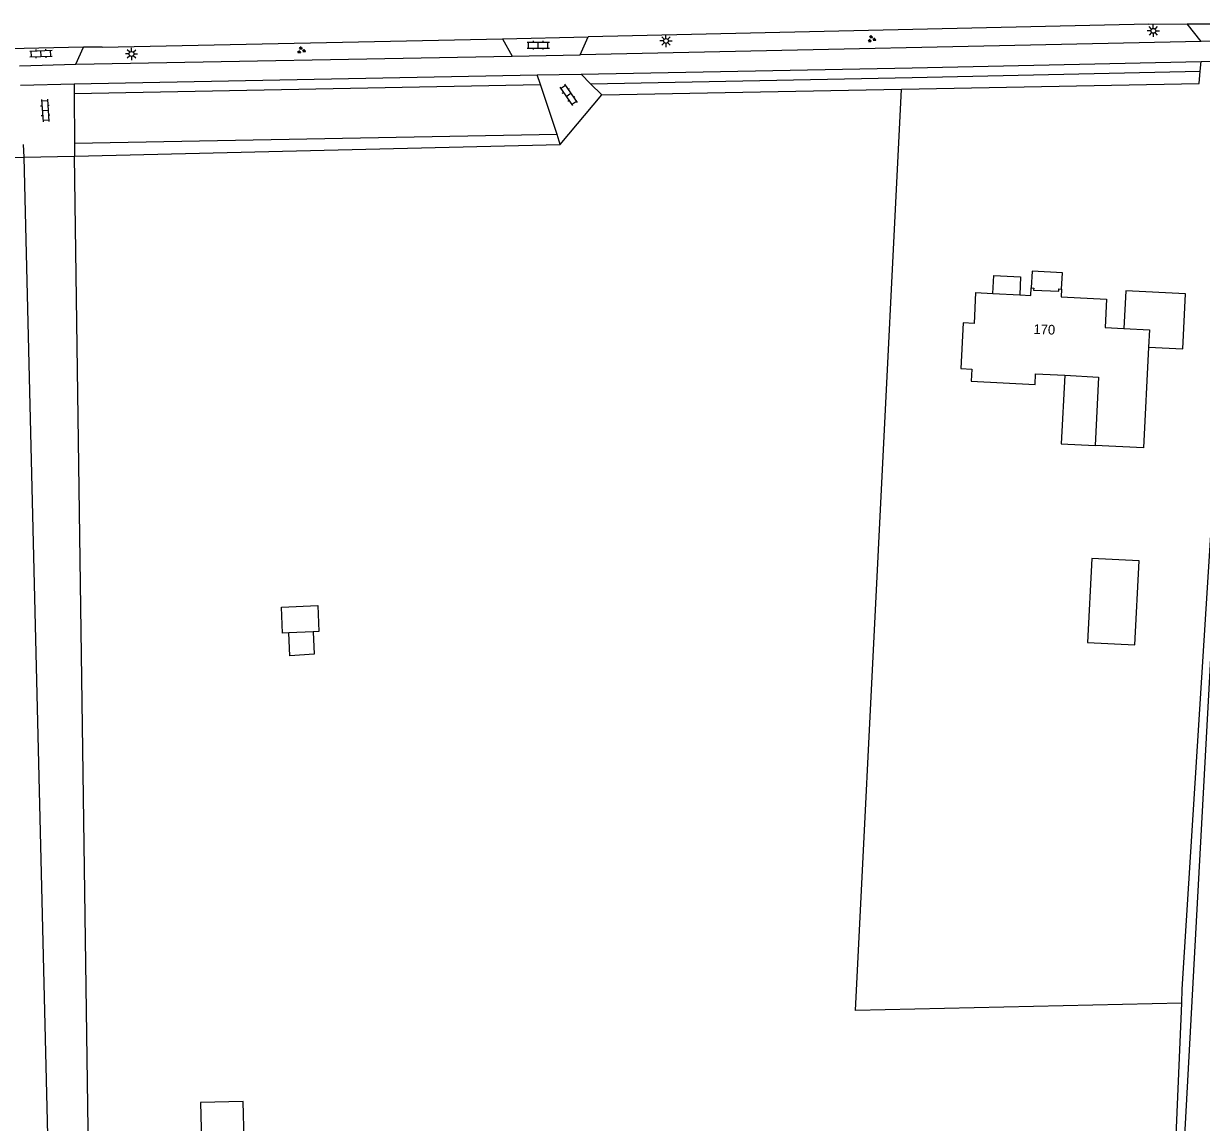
# Model space of a CAD drawing. Extents: x 128999 to 131010, y 395498 to 399007.
# Drawn here: x 130782.7 to 130904.2, y 396021.5 to 396134.9 of the extents above; entities that cross this region are included whole.
import ezdxf

# ---------------------------------------------------------------- set-up
doc = ezdxf.new("R2010")
doc.units = 0
for name, color, linetype in [('gg-afsc-erfafscheiding', 7, 'Continuous'), ('gg-anno-huisnummerreeks BGT', 7, 'Continuous'), ('gg-bbg-bijgebouw', 7, 'Continuous'), ('gg-bbg-gedigitaliseerde bebouwing', 7, 'Continuous'), ('gg-bbg-gedigitaliseerde bijgebouw', 7, 'Continuous'), ('gg-bbg-hoofdgebouw', 7, 'Continuous'), ('gg-bbg-luifel en loopbrug', 7, 'Continuous'), ('gg-knt-onverhard', 7, 'Continuous'), ('gg-knt-verharding', 7, 'Continuous'), ('gt-grn-groengrens', 7, 'Continuous'), ('gt-grn-groengrens NZ', 7, 'Continuous'), ('gt-symb-groenvak', 7, 'Continuous'), ('gt-symb-klinker verharding', 7, 'Continuous'), ('gt-symb-lichtmast', 7, 'Continuous')]:
    doc.layers.add(name, color=color, linetype=linetype)

# ---------------------------------------------------------------- blocks, each defined once
blk = doc.blocks.new('gt0-LMAST')
at = {"layer": 'gt-symb-lichtmast'}
for p, q in [((-0.18, 0.17), (-0.45, 0.44)), ((-0.01, 0.25), (-0.01, 0.62)), ((0.17, 0.17), (0.44, 0.44)), ((-0.26, 0), (-0.63, 0)), ((-0.18, -0.18), (-0.45, -0.45)), ((-0.01, -0.25), (-0.01, -0.63)), ((0.44, -0.45), (0.17, -0.18)), ((0.24, 0), (0.62, 0))]:
    blk.add_line(p, q, dxfattribs=at)
blk.add_circle((-0.01, 0), 0.25, dxfattribs=at)
blk = doc.blocks.new('gt0-GRVAK')
at = {"layer": 'gt-symb-groenvak'}
for p, q in [((-0.11, 0.19), (-0.23, 0.24)), ((-0.18, 0.15), (0.09, 0.15)), ((-0.09, 0.21), (-0.16, 0.32)), ((-0.05, 0.21), (-0.05, 0.39)), ((0, 0.21), (0.06, 0.32)), ((0.01, 0.19), (0.13, 0.24)), ((0.26, -0.05), (0.2, 0.06)), ((0.31, -0.05), (0.31, 0.13)), ((0.35, -0.05), (0.41, 0.06)), ((-0.24, -0.23), (-0.36, -0.18)), ((-0.32, -0.26), (-0.05, -0.26)), ((-0.23, -0.21), (-0.29, -0.1)), ((-0.18, -0.2), (-0.18, -0.02)), ((-0.14, -0.21), (-0.07, -0.1)), ((-0.12, -0.23), (0, -0.18)), ((0.24, -0.07), (0.12, -0.02)), ((0.17, -0.11), (0.44, -0.11)), ((0.37, -0.07), (0.49, -0.02))]:
    blk.add_line(p, q, dxfattribs=at)
blk = doc.blocks.new('gt0-KL1')
at = {"layer": 'gt-symb-klinker verharding'}
for p, q in [((-1.15, 0.3), (1.15, 0.3)), ((-1, -0.3), (-1, 0.3)), ((-0.5, 0.3), (-0.5, 0.45)), ((0, -0.3), (0, 0.3)), ((0.5, 0.3), (0.5, 0.45)), ((1, -0.3), (1, 0.3)), ((-1.15, -0.3), (1.15, -0.3)), ((-0.5, -0.45), (-0.5, -0.3)), ((0.5, -0.45), (0.5, -0.3))]:
    blk.add_line(p, q, dxfattribs=at)

msp = doc.modelspace()

# ---------------------------------------------------------------- linework, layer by layer
at = {"layer": 'gg-afsc-erfafscheiding'}
for p, q in [((130904.11, 396129.95), (130904.21, 396130.96)), ((130838.09, 396122.39), (130842.37, 396127.52)), ((130842.37, 396127.52), (130873.31, 396128.1)), ((130787.97, 396121.19), (130838.09, 396122.39)), ((130782.76, 396121.07), (130787.97, 396121.19))]:
    msp.add_line(p, q, dxfattribs=at)
for points in [[(130873.31, 396128.1), (130903.99, 396128.67), (130904.11, 396129.95)], [(130902.2, 396033.79), (130902.26, 396035.23), (130908.12, 396128.45), (130908.24, 396131.04)], [(130742.42, 396120.7), (130773.27, 396120.84), (130782.76, 396121.07)], [(130898.84, 395964.32), (130900.77, 396000), (130902.2, 396033.79)]]:
    msp.add_lwpolyline(points, dxfattribs=at)
at = {"layer": 'gg-bbg-bijgebouw'}
msp.add_line((130812.6, 396072.09), (130810.09, 396071.98), dxfattribs=at)
for points in [[(130810.09, 396071.98), (130809.45, 396071.95), (130809.33, 396074.64), (130813.08, 396074.82), (130813.2, 396072.12), (130812.6, 396072.09)], [(130801.19, 396015.53), (130805.6, 396015.65), (130805.4, 396023.65), (130800.99, 396023.54), (130801.19, 396015.53)]]:
    msp.add_lwpolyline(points, dxfattribs=at)
at = {"layer": 'gg-bbg-gedigitaliseerde bebouwing'}
msp.add_line((130898.26, 396091.09), (130893.26, 396091.34), dxfattribs=at)
for points in [[(130880.94, 396107.1), (130880.79, 396103.92), (130879.66, 396103.97), (130879.42, 396099.28), (130880.55, 396099.22), (130880.49, 396097.95), (130887.08, 396097.62), (130887.13, 396098.72), (130890.13, 396098.57)], [(130890.13, 396098.57), (130893.62, 396098.39), (130893.26, 396091.34)]]:
    msp.add_lwpolyline(points, dxfattribs=at)
at = {"layer": 'gg-bbg-gedigitaliseerde bijgebouw'}
msp.add_lwpolyline([(130892.92, 396079.67), (130892.48, 396071), (130897.38, 396070.76), (130897.81, 396079.42), (130892.92, 396079.67)], dxfattribs=at)
at = {"layer": 'gg-bbg-hoofdgebouw'}
for p, q in [((130880.94, 396107.1), (130882.73, 396107.01)), ((130882.73, 396107.01), (130885.49, 396106.87)), ((130898.78, 396101.47), (130898.26, 396091.09))]:
    msp.add_line(p, q, dxfattribs=at)
for points in [[(130885.49, 396106.87), (130886.63, 396106.81), (130886.67, 396107.58)], [(130886.67, 396107.58), (130886.94, 396107.57), (130886.93, 396107.35), (130889.52, 396107.26), (130889.53, 396107.48), (130889.8, 396107.46)], [(130889.8, 396107.46), (130889.76, 396106.65), (130894.43, 396106.41), (130894.29, 396103.49), (130896.23, 396103.39)], [(130896.23, 396103.39), (130898.87, 396103.26), (130898.78, 396101.47)]]:
    msp.add_lwpolyline(points, dxfattribs=at)
at = {"layer": 'gg-bbg-luifel en loopbrug'}
for points in [[(130889.8, 396107.46), (130889.89, 396109.16), (130886.76, 396109.31), (130886.67, 396107.58)], [(130882.73, 396107.01), (130882.82, 396108.87), (130885.58, 396108.73), (130885.49, 396106.87)], [(130898.78, 396101.47), (130902.32, 396101.29), (130902.6, 396106.97), (130896.43, 396107.28), (130896.23, 396103.39)], [(130890.13, 396098.57), (130889.78, 396091.51), (130893.26, 396091.34)], [(130812.6, 396072.09), (130812.71, 396069.79), (130810.2, 396069.63), (130810.09, 396071.98)]]:
    msp.add_lwpolyline(points, dxfattribs=at)
at = {"layer": 'gg-knt-onverhard'}
msp.add_line((130782.76, 396121.07), (130786.57, 395964.38), dxfattribs=at)
msp.add_lwpolyline([(130786.57, 395964.38), (130790.19, 395964.46), (130787.97, 396121.19)], dxfattribs=at)
at = {"layer": 'gg-knt-verharding'}
for p, q in [((130898.82, 396134.8), (130840.97, 396133.49)), ((130898.82, 396134.8), (130902.78, 396134.82)), ((130902.78, 396134.82), (130908.96, 396134.86)), ((130904.22, 396133.01), (130902.78, 396134.82)), ((130788.9, 396132.43), (130781.24, 396132.25)), ((130788.12, 396130.66), (130788.9, 396132.43)), ((130790.84, 396132.42), (130832.14, 396133.3)), ((130832.14, 396133.3), (130840.97, 396133.49)), ((130832.14, 396133.3), (130833.14, 396131.49)), ((130840.14, 396131.64), (130840.97, 396133.49)), ((130904.22, 396133.01), (130840.14, 396131.64)), ((130907.53, 396133.09), (130904.22, 396133.01)), ((130788.12, 396130.66), (130833.14, 396131.49)), ((130833.14, 396131.49), (130840.14, 396131.64)), ((130782.3, 396130.51), (130788.12, 396130.66)), ((130904.21, 396130.96), (130908.24, 396131.04)), ((130782.4, 396128.5), (130787.95, 396128.65)), ((130787.95, 396128.65), (130835.73, 396129.56)), ((130787.95, 396128.65), (130787.95, 396127.65)), ((130835.73, 396129.56), (130840.25, 396129.64)), ((130836.06, 396128.56), (130835.73, 396129.56)), ((130841.23, 396128.66), (130840.25, 396129.64)), ((130842.37, 396127.52), (130841.23, 396128.66)), ((130787.95, 396127.65), (130787.97, 396122.49)), ((130837.76, 396123.41), (130836.06, 396128.56)), ((130838.09, 396122.39), (130837.76, 396123.41)), ((130782.7, 396122.39), (130782.76, 396121.07)), ((130787.97, 396122.49), (130787.97, 396121.19))]:
    msp.add_line(p, q, dxfattribs=at)
for points in [[(130790.84, 396132.42), (130789.62, 396132.44), (130788.9, 396132.43)], [(130840.25, 396129.64), (130874.38, 396130.3), (130904.21, 396130.96)]]:
    msp.add_lwpolyline(points, dxfattribs=at)
at = {"layer": 'gt-grn-groengrens'}
msp.add_line((130837.76, 396123.41), (130787.97, 396122.49), dxfattribs=at)
for points in [[(130902.2, 396033.79), (130868.56, 396033.03), (130873.31, 396128.1)], [(130907.75, 396116.77), (130902.42, 396018.83), (130901.43, 396000), (130899.51, 395964.29)]]:
    msp.add_lwpolyline(points, dxfattribs=at)
at = {"layer": 'gt-grn-groengrens NZ'}
msp.add_line((130787.95, 396127.65), (130836.06, 396128.56), dxfattribs=at)
msp.add_lwpolyline([(130841.23, 396128.66), (130874.4, 396129.3), (130904.11, 396129.95)], dxfattribs=at)

# ---------------------------------------------------------------- block references
at = {"layer": 'gt-symb-groenvak'}
for p, rotation in [((130870.21, 396133.27), -2.9796737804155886), ((130811.37, 396132.11), -2.9796737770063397)]:
    msp.add_blockref('gt0-GRVAK', p, dxfattribs=dict(at, rotation=rotation))
at = {"layer": 'gt-symb-klinker verharding'}
msp.add_blockref('gt0-KL1', (130835.82, 396132.64), dxfattribs=at)
for p, rotation in [((130784.53, 396131.77), 2.063819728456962), ((130838.95, 396127.51), -55.46787543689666), ((130784.97, 396125.9), -86.04496236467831)]:
    msp.add_blockref('gt0-KL1', p, dxfattribs=dict(at, rotation=rotation))
at = {"layer": 'gt-symb-lichtmast'}
for p in [(130899.28, 396134.12), (130849.01, 396133.07), (130793.87, 396131.73)]:
    msp.add_blockref('gt0-LMAST', p, dxfattribs=at)

# ---------------------------------------------------------------- texts
at = {"layer": 'gg-anno-huisnummerreeks BGT'}
msp.add_text('170', height=1, rotation=358, dxfattribs=at).set_placement((130886.9, 396102.84))

doc.saveas('drawing.dxf')
